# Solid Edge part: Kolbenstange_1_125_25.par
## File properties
Username: ahadarics
Dokumentum tartalom típus: 0
Author: ahadarics
Last saved by: ahadarics
Revision: 78
Sűrűség: 0,000 kg/m^3
Pontosság: 0,990
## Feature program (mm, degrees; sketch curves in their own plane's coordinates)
base feature "unnamed BaseFeature 1"
thread "unnamed Thread 1"
chamfer "Letörés_1"  SetBackValue2 = 25 deg
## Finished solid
Body 1: solid body, 19 faces, 27 edges, 11 vertices.
  Faces by surface: plane 8, cylinder 5, cone 3, torus 3
  Edges by curve: circle 15, line 7, curve on surface 3, ellipse 2
Bounding box of the edges (mm; curved faces can reach further): 125.000 x 125.000 x 257.000, from (-62.5, -62.5, -108.5) to (62.5, 62.5, 148.5).
Cylindrical faces by radius (mm): R11.9 x1, R13.5 x1, R15.5 x1, R16 x1, R62.5 x1
Conical faces (half-angle, radius in mm at the cone's reference point): 25 deg R13.5 x1, 30 deg R15.75 x1, 60 deg R12.7 x1
Toroidal faces (ring radius, tube radius in mm): R12.7 r0.8 x2, R13.3 r2.2 x1
Planar faces by outward normal: +x 1, +z 3, -x 1, -z 1, oblique 2
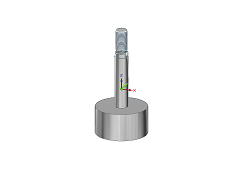
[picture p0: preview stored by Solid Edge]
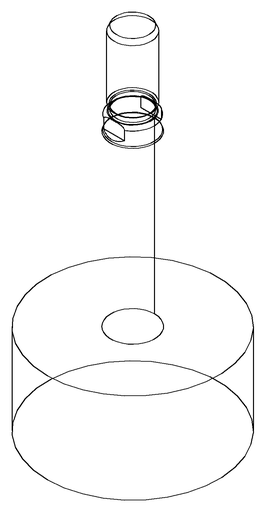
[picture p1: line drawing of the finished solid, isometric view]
